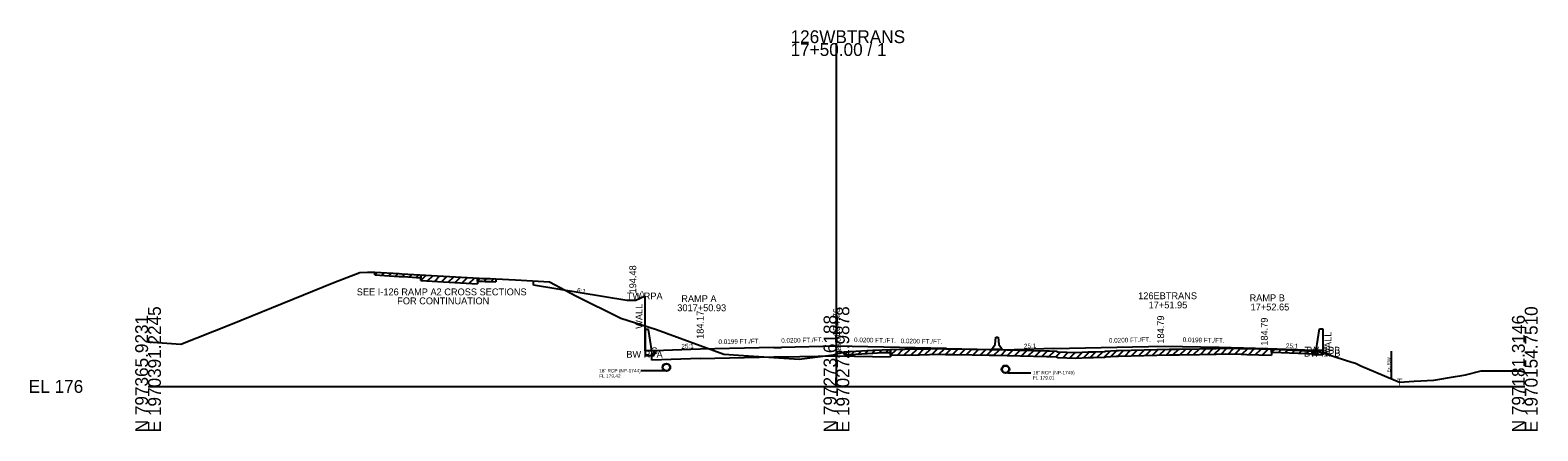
# Model space of a CAD drawing. Extents: x -6494 to 1970605, y -10 to 798140.
# Drawn here: x 974.3 to 1302.8, y -9.7 to 77.8 of the extents above; entities that cross this region are included whole.
import ezdxf

# ---------------------------------------------------------------- set-up
doc = ezdxf.new("R2010")
doc.units = 0
for name, color, linetype in [('Default', 7, 'Continuous'), ('RD_EX_SU_Misc_TxCode', 7, 'Continuous'), ('RD_GPK_XS_Cell', 7, 'Continuous'), ('RD_Sketch1', 7, 'Continuous'), ('RD_XS_Base', 7, 'Continuous'), ('RD_XS_Box', 7, 'Continuous'), ('RD_XS_EwShp', 7, 'Continuous'), ('RD_XS_ExGround', 7, 'Continuous'), ('RD_XS_ExPaveRet', 7, 'Continuous'), ('RD_XS_ExRW', 7, 'Continuous'), ('RD_XS_MedBWall', 7, 'Continuous'), ('RD_XS_Misc_Line', 7, 'Continuous'), ('RD_XS_Pave', 7, 'Continuous'), ('RD_XS_PaveOvlay', 7, 'Continuous'), ('RD_XS_PaveShd', 7, 'Continuous'), ('RD_XS_Pipe', 7, 'Continuous'), ('RD_XS_TieSlope', 7, 'Continuous'), ('RD_XS_TX_Elev_EX', 7, 'Continuous'), ('RD_XS_TX_Elev_PR', 7, 'Continuous'), ('RD_XS_TX_Misc', 7, 'Continuous'), ('RD_XS_TX_Notes', 7, 'Continuous'), ('RD_XS_TX_Profile', 7, 'Continuous'), ('RD_XS_TX_Slope', 7, 'Continuous'), ('RD_XS_TX_Station', 7, 'Continuous')]:
    doc.layers.add(name, color=color, linetype=linetype)

msp = doc.modelspace()

# ---------------------------------------------------------------- linework, layer by layer
at = {"layer": 'Default'}
for p, q in [((1184.58, 9.18), (1184.75, 10.77)), ((1184.75, 10.77), (1185.25, 10.77)), ((1185.25, 10.77), (1185.42, 9.18)), ((1184, 8.35), (1184.58, 9.18)), ((1184, 8.1), (1184, 8.35)), ((1186, 8.1), (1184, 8.1)), ((1185.42, 9.18), (1186, 8.35)), ((1186, 8.35), (1186, 8.1))]:
    msp.add_line(p, q, dxfattribs=at)
at = {"layer": 'RD_GPK_XS_Cell'}
for p, q in [((1150, 0), (1150, 74.92)), ((1000, 0), (1150, 0)), ((1150, 0), (1300, 0))]:
    msp.add_line(p, q, dxfattribs=at)
at = {"layer": 'RD_XS_Base'}
for p, q in [((1109.79, 7.19), (1110.29, 7.21)), ((1109.79, 5.71), (1109.79, 7.19)), ((1110.29, 7.21), (1110.29, 7.77)), ((1138, 6.48), (1150, 6.72)), ((1150, 6.72), (1161.78, 6.49)), ((1254.02, 7.72), (1254.02, 7.94)), ((1254.02, 7.38), (1254.02, 7.94)), ((1120.31, 6.13), (1109.79, 5.71)), ((1120.31, 6.13), (1136.33, 6.45)), ((1136.33, 6.45), (1138, 6.48))]:
    msp.add_line(p, q, dxfattribs=at)
at = {"layer": 'RD_XS_Box'}
for p, q in [((1108.29, 7.77), (1108.29, 19.73)), ((1110.29, 7.77), (1108.29, 7.77)), ((1254.02, 7.94), (1256.03, 7.94)), ((1256.03, 7.94), (1256.03, 7.3))]:
    msp.add_line(p, q, dxfattribs=at)
at = {"layer": 'RD_XS_ExGround'}
msp.add_lwpolyline([(1000, 9.72), (1007.13, 9.22), (1017.96, 13.51), (1040.47, 22.69), (1046.17, 24.84), (1047.78, 24.92), (1049.42, 24.97), (1054.7, 24.64), (1055.28, 24.61), (1056.64, 24.53), (1072.16, 23.61), (1072.89, 23.59), (1073.44, 23.57), (1074.56, 23.53), (1075.75, 23.49), (1080.09, 23.24), (1087.46, 22.8), (1093.19, 19.76), (1103.04, 14.89), (1110.8, 12.4), (1125.45, 7.04), (1129.74, 6.74), (1141.91, 5.94), (1148.78, 6.85), (1149.35, 6.93), (1150, 7.09), (1150.71, 7.27), (1151.78, 7.53), (1157.93, 7.91), (1159.93, 8.03), (1161.74, 8.07), (1168.1, 8.18), (1170.27, 8.23), (1172, 8.27), (1173.79, 8.24), (1175.78, 8.2), (1183.25, 8.08), (1183.66, 8.07), (1184.33, 8.06), (1195.8, 7.81), (1196.44, 7.78), (1197.98, 7.7), (1198.26, 7.58), (1202.17, 7.4), (1204.84, 7.54), (1206.03, 7.59), (1208.43, 7.66), (1208.65, 7.74), (1210.98, 7.85), (1211.46, 7.86), (1222.55, 8.12), (1224.74, 8.15), (1229.1, 8.24), (1232.76, 8.29), (1234.77, 8.34), (1238.21, 8.27), (1239.43, 8.25), (1242.05, 8.18), (1246.88, 8.05), (1252.46, 7.8), (1254.81, 7.69), (1260.71, 5.82), (1262.32, 5.31), (1263.07, 5.08), (1264.29, 4.52), (1272.67, 0.96), (1275.87, 1.15), (1280.16, 1.41), (1284.88, 2.16), (1286.27, 2.37), (1287.09, 2.57), (1290.51, 3.41), (1296.88, 3.41), (1299.09, 3.41), (1300, 3.1)], dxfattribs=at)
at = {"layer": 'RD_XS_ExPaveRet'}
for p, q in [((1049.42, 24.35), (1049.42, 24.97)), ((1049.42, 24.35), (1054.7, 24.02)), ((1054.7, 24.02), (1055.28, 23.98)), ((1055.28, 23.98), (1056.64, 23.9)), ((1056.64, 23.9), (1059.42, 23.74)), ((1059.42, 23.11), (1059.42, 24.36)), ((1059.42, 24.36), (1059.42, 23.74)), ((1059.42, 23.11), (1071.75, 22.39)), ((1071.75, 23.64), (1071.75, 22.39)), ((1071.75, 23.01), (1071.75, 23.64)), ((1071.75, 23.01), (1072.16, 22.99)), ((1075.75, 23.49), (1075.75, 22.86)), ((1072.16, 22.99), (1072.89, 22.96)), ((1072.89, 22.96), (1073.44, 22.94)), ((1073.44, 22.94), (1074.56, 22.9)), ((1074.56, 22.9), (1075.75, 22.86)), ((1151.78, 6.91), (1151.78, 7.53)), ((1151.78, 6.91), (1157.93, 7.29)), ((1157.93, 7.29), (1159.93, 7.41)), ((1159.93, 7.41), (1161.74, 7.44)), ((1161.74, 7.44), (1161.78, 7.45)), ((1161.78, 6.82), (1161.78, 8.07)), ((1161.78, 8.07), (1161.78, 7.45)), ((1161.78, 6.82), (1168.1, 6.93)), ((1168.1, 6.93), (1170.27, 6.98)), ((1170.27, 6.98), (1172, 7.02)), ((1172, 7.02), (1173.79, 6.99)), ((1173.79, 6.99), (1175.78, 6.95)), ((1175.78, 6.95), (1183.25, 6.83)), ((1183.25, 6.83), (1183.66, 6.82)), ((1183.66, 6.82), (1184.33, 6.81)), ((1184.33, 6.81), (1195.8, 6.56)), ((1208.65, 6.49), (1210.98, 6.6)), ((1210.98, 6.6), (1211.46, 6.61)), ((1211.46, 6.61), (1222.55, 6.87)), ((1222.55, 6.87), (1224.74, 6.9)), ((1224.74, 6.9), (1229.1, 6.99)), ((1229.1, 6.99), (1232.76, 7.04)), ((1232.76, 7.04), (1234.77, 7.09)), ((1234.77, 7.09), (1238.21, 7.02)), ((1238.21, 7.02), (1239.43, 7)), ((1239.43, 7), (1242.05, 6.93)), ((1242.05, 6.93), (1244.81, 6.86)), ((1244.81, 8.11), (1244.81, 6.86)), ((1244.81, 7.48), (1244.81, 8.11)), ((1244.81, 7.48), (1246.88, 7.43)), ((1246.88, 7.43), (1252.46, 7.18)), ((1252.46, 7.18), (1254.81, 7.06)), ((1254.81, 7.69), (1254.81, 7.06)), ((1195.8, 6.56), (1196.44, 6.53)), ((1196.44, 6.53), (1197.98, 6.45)), ((1197.98, 6.45), (1198.26, 6.33)), ((1198.26, 6.33), (1202.17, 6.15)), ((1202.17, 6.15), (1204.84, 6.29)), ((1204.84, 6.29), (1206.03, 6.34)), ((1206.03, 6.34), (1208.43, 6.41)), ((1208.43, 6.41), (1208.65, 6.49))]:
    msp.add_line(p, q, dxfattribs=at)
at = {"layer": 'RD_XS_ExRW'}
msp.add_line((1270.91, 7.7), (1270.91, 1.7), dxfattribs=at)
at = {"layer": 'RD_XS_MedBWall'}
for p, q in [((1109.04, 12.44), (1108.29, 12.44)), ((1108.29, 12.44), (1108.29, 6.77)), ((1109.79, 7.77), (1109.04, 12.44)), ((1254.52, 7.94), (1255.27, 12.6)), ((1255.27, 12.6), (1256.02, 12.6)), ((1256.02, 12.6), (1256.02, 6.94)), ((1108.29, 6.77), (1110.29, 6.77)), ((1110.29, 7.77), (1109.79, 7.77)), ((1110.29, 6.77), (1110.29, 7.77)), ((1254.02, 6.94), (1254.02, 7.94)), ((1254.02, 7.94), (1254.52, 7.94)), ((1256.02, 6.94), (1254.02, 6.94))]:
    msp.add_line(p, q, dxfattribs=at)
at = {"layer": 'RD_XS_Misc_Line'}
for p, q in [((1049.42, 24.35), (1050, 24.94)), ((1050.92, 24.26), (1051.51, 24.84)), ((1052.42, 24.16), (1053.01, 24.75)), ((1053.92, 24.07), (1054.51, 24.66)), ((1055.42, 23.98), (1056.01, 24.56)), ((1056.92, 23.88), (1057.51, 24.47)), ((1058.42, 23.8), (1059.01, 24.39)), ((1059.42, 23.11), (1060.6, 24.29)), ((1060.92, 23.02), (1062.1, 24.2)), ((1062.42, 22.94), (1063.6, 24.12)), ((1063.92, 22.85), (1065.11, 24.03)), ((1065.43, 22.76), (1066.61, 23.94)), ((1066.93, 22.67), (1068.11, 23.85)), ((1068.43, 22.58), (1069.61, 23.76)), ((1069.93, 22.49), (1071.11, 23.67)), ((1071.75, 23.01), (1072.34, 23.61)), ((1073.25, 22.95), (1073.85, 23.55)), ((1074.75, 22.9), (1075.35, 23.5)), ((1151.78, 6.91), (1152.45, 7.58)), ((1153.29, 7), (1153.95, 7.67)), ((1154.79, 7.1), (1155.45, 7.76)), ((1156.29, 7.19), (1156.95, 7.85)), ((1157.79, 7.28), (1158.45, 7.95)), ((1159.29, 7.37), (1159.95, 8.03)), ((1160.79, 7.43), (1161.43, 8.06)), ((1161.78, 6.82), (1163.06, 8.09)), ((1163.29, 6.85), (1164.56, 8.12)), ((1164.79, 6.87), (1166.06, 8.14)), ((1166.29, 6.9), (1167.56, 8.17)), ((1167.79, 6.92), (1169.07, 8.2)), ((1169.29, 6.96), (1170.57, 8.24)), ((1170.79, 6.99), (1172.07, 8.27)), ((1172.29, 7.02), (1173.52, 8.24)), ((1173.79, 6.99), (1175.02, 8.22)), ((1175.29, 6.96), (1176.52, 8.19)), ((1176.79, 6.94), (1178.02, 8.17)), ((1178.29, 6.91), (1179.52, 8.14)), ((1179.8, 6.89), (1181.02, 8.11)), ((1181.3, 6.86), (1182.53, 8.09)), ((1182.8, 6.83), (1184.03, 8.06)), ((1184.3, 6.81), (1185.52, 8.03)), ((1185.8, 6.77), (1187.02, 8)), ((1187.3, 6.74), (1188.52, 7.97)), ((1188.8, 6.71), (1190.03, 7.93)), ((1190.3, 6.68), (1191.53, 7.9)), ((1191.8, 6.65), (1193.03, 7.87)), ((1193.3, 6.62), (1194.53, 7.84)), ((1194.8, 6.58), (1196.02, 7.8)), ((1196.3, 6.54), (1197.49, 7.73)), ((1197.81, 6.46), (1198.9, 7.55)), ((1199.31, 6.28), (1200.5, 7.48)), ((1200.81, 6.21), (1202, 7.41)), ((1202.31, 6.16), (1203.63, 7.47)), ((1203.81, 6.23), (1205.12, 7.55)), ((1205.31, 6.31), (1206.61, 7.6)), ((1206.81, 6.36), (1208.1, 7.65)), ((1208.31, 6.41), (1209.7, 7.79)), ((1209.81, 6.55), (1211.12, 7.85)), ((1211.31, 6.61), (1212.59, 7.89)), ((1212.81, 6.64), (1214.09, 7.92)), ((1214.31, 6.68), (1215.6, 7.96)), ((1215.82, 6.71), (1217.1, 7.99)), ((1217.32, 6.75), (1218.6, 8.03)), ((1218.82, 6.78), (1220.1, 8.06)), ((1220.32, 6.82), (1221.6, 8.1)), ((1221.82, 6.85), (1223.09, 8.12)), ((1223.32, 6.88), (1224.59, 8.14)), ((1224.82, 6.9), (1226.1, 8.17)), ((1226.32, 6.93), (1227.6, 8.21)), ((1227.82, 6.96), (1229.1, 8.24)), ((1229.32, 6.99), (1230.59, 8.26)), ((1230.82, 7.01), (1232.09, 8.28)), ((1232.33, 7.03), (1233.6, 8.31)), ((1233.83, 7.06), (1235.09, 8.33)), ((1235.33, 7.07), (1236.55, 8.3)), ((1236.83, 7.05), (1238.05, 8.27)), ((1238.33, 7.02), (1239.55, 8.24)), ((1239.83, 6.99), (1241.05, 8.2)), ((1241.33, 6.95), (1242.55, 8.16)), ((1242.83, 6.91), (1244.05, 8.13)), ((1244.81, 7.48), (1245.42, 8.09)), ((1246.31, 7.44), (1246.92, 8.05)), ((1247.81, 7.39), (1248.41, 7.98)), ((1249.32, 7.32), (1249.91, 7.92)), ((1250.82, 7.25), (1251.41, 7.85)), ((1252.32, 7.18), (1252.91, 7.78)), ((1253.82, 7.11), (1254.41, 7.71))]:
    msp.add_line(p, q, dxfattribs=at)
at = {"layer": 'RD_XS_Pave'}
for p, q in [((1136.33, 8.49), (1120.31, 8.17)), ((1150, 8.76), (1138, 8.52)), ((1174, 8.28), (1150, 8.76)), ((1197.4, 8.31), (1221.4, 8.79)), ((1221.4, 8.79), (1233.4, 8.55)), ((1233.4, 8.55), (1243.99, 8.31))]:
    msp.add_line(p, q, dxfattribs=at)
at = {"layer": 'RD_XS_PaveOvlay'}
for p, q in [((1161.78, 8.07), (1168.1, 8.18)), ((1161.78, 8.07), (1161.78, 6.49)), ((1168.1, 8.18), (1170.27, 8.23)), ((1170.27, 8.23), (1172, 8.27)), ((1172, 8.27), (1173.79, 8.24)), ((1173.79, 8.24), (1175.78, 8.2)), ((1175.78, 8.2), (1183.25, 8.08)), ((1183.25, 8.08), (1183.66, 8.07)), ((1183.66, 8.07), (1184.33, 8.06)), ((1184.33, 8.06), (1195.8, 7.81)), ((1195.8, 7.81), (1196.44, 7.78)), ((1196.44, 7.78), (1197.98, 7.7)), ((1197.98, 7.7), (1198.26, 7.58)), ((1198.26, 7.58), (1202.17, 7.4)), ((1202.17, 7.4), (1204.84, 7.54)), ((1204.84, 7.54), (1206.03, 7.59)), ((1206.03, 7.59), (1208.43, 7.66)), ((1208.43, 7.66), (1208.65, 7.74)), ((1208.65, 7.74), (1210.98, 7.85)), ((1210.98, 7.85), (1211.46, 7.86)), ((1211.46, 7.86), (1222.55, 8.12)), ((1222.55, 8.12), (1224.74, 8.15)), ((1224.74, 8.15), (1229.1, 8.24)), ((1229.1, 8.24), (1232.76, 8.29)), ((1232.76, 8.29), (1234.77, 8.34)), ((1234.77, 8.34), (1238.21, 8.27)), ((1238.21, 8.27), (1239.43, 8.25)), ((1239.43, 8.25), (1242.05, 8.18)), ((1242.05, 8.18), (1244.81, 8.11)), ((1244.81, 8.11), (1246.88, 8.05)), ((1246.88, 8.05), (1249.67, 7.93)), ((1249.67, 7.93), (1252.46, 7.8)), ((1252.46, 7.8), (1253.64, 7.74)), ((1253.64, 7.74), (1254.02, 7.72))]:
    msp.add_line(p, q, dxfattribs=at)
at = {"layer": 'RD_XS_PaveShd'}
for p, q in [((1120.31, 8.17), (1110.29, 7.77)), ((1136.33, 8.49), (1138, 8.52)), ((1174, 8.28), (1184, 8.06)), ((1184, 8.06), (1188.75, 7.96)), ((1197.4, 8.31), (1188.75, 7.96)), ((1243.99, 8.31), (1254.02, 7.91))]:
    msp.add_line(p, q, dxfattribs=at)
at = {"layer": 'RD_XS_Pipe'}
for p, q in [((1112.45, 3.42), (1107.45, 3.42)), ((1187.35, 3.01), (1192.35, 3.01))]:
    msp.add_line(p, q, dxfattribs=at)
for centre, radius in [((1112.95, 4.17), 0.85), ((1112.95, 4.17), 0.75), ((1186.85, 3.76), 0.85), ((1186.85, 3.76), 0.75)]:
    msp.add_circle(centre, radius, dxfattribs=at)
at = {"layer": 'RD_XS_TieSlope'}
for p, q in [((1083.97, 22.12), (1083.97, 23.01)), ((1104.29, 18.73), (1083.97, 22.12)), ((1108.29, 19.73), (1106.29, 18.73)), ((1106.29, 18.73), (1104.29, 18.73))]:
    msp.add_line(p, q, dxfattribs=at)

# ---------------------------------------------------------------- texts
at = {"layer": 'RD_EX_SU_Misc_TxCode'}
msp.add_text('G', height=1.5, dxfattribs=at).set_placement((1109.54, 7.02))
at = {"layer": 'RD_GPK_XS_Cell'}
for s, p in [('126WBTRANS', (1140, 74.92)), ('17+50.00 / 1', (1140, 72.12)), ('EL 176', (974, -1.4))]:
    msp.add_text(s, height=2.8, dxfattribs=at).set_placement(p)
for s, p in [('E 1970391.2245', (1002.8, -10)), ('E 1970272.9878', (1152.8, -10)), ('E 1970154.7510', (1302.8, -10)), ('N 797365.9231', (1000, -10)), ('N 797273.6188', (1150, -10)), ('N 797181.3146', (1300, -10))]:
    msp.add_text(s, height=2.8, rotation=90, dxfattribs=at).set_placement(p)
at = {"layer": 'RD_Sketch1'}
msp.add_text('T', height=1.5, dxfattribs=at).set_placement((1272.12, 0.21))
at = {"layer": 'RD_XS_EwShp'}
for s, p in [('TW RPA', (1104.33, 18.98)), ('BW RPA', (1104.22, 6.27)), ('TW RPB', (1252, 7.16)), ('BW RPB', (1251.9, 6.52))]:
    msp.add_text(s, height=1.5, dxfattribs=at).set_placement(p)
at = {"layer": 'RD_XS_ExRW'}
msp.add_text('Ex. R/W ', height=0.65, rotation=90, dxfattribs=at).set_placement((1270.66, 3.09))
at = {"layer": 'RD_XS_Pipe'}
for s, p in [('18" RCP (NP-1744)', (1098.3, 3.05)), ('18" RCP (NP-1749)', (1192.85, 2.64)), ('FL 179.42', (1098.3, 1.92)), ('FL 179.01', (1192.85, 1.51))]:
    msp.add_text(s, height=0.75, dxfattribs=at).set_placement(p)
at = {"layer": 'RD_XS_TX_Elev_EX'}
msp.add_text('183.09', height=1, rotation=90, dxfattribs=at).set_placement((1151, 7.09))
at = {"layer": 'RD_XS_TX_Elev_PR'}
for s, p in [('184.76', (1150.75, 10.98)), ('184.17', (1121.06, 10.38)), (' 184.79', (1221.4, 8.79)), (' 184.79', (1243.99, 8.34))]:
    msp.add_text(s, height=1.5, rotation=90, dxfattribs=at).set_placement(p)
at = {"layer": 'RD_XS_TX_Misc'}
msp.add_text('194.48', height=1.5, rotation=90, dxfattribs=at).set_placement((1106.37, 20.31))
at = {"layer": 'RD_XS_TX_Notes'}
for s, p in [('SEE I-126 RAMP A2 CROSS SECTIONS', (1045.48, 19.89)), ('FOR CONTINUATION', (1054.29, 17.93))]:
    msp.add_text(s, height=1.5, dxfattribs=at).set_placement(p)
for p in [(1107.72, 12.58), (1257.84, 6.5)]:
    msp.add_text('WALL', height=1.5, rotation=90, dxfattribs=at).set_placement(p)
at = {"layer": 'RD_XS_TX_Profile'}
for rotation, p in [(2.2905, (1190.88, 8.3)), (357.7094, (1247.93, 8.4))]:
    msp.add_text('25:1', height=1, rotation=rotation, dxfattribs=at).set_placement(p)
at = {"layer": 'RD_XS_TX_Slope'}
for s, rotation, p in [('6:1', 350.5377, (1093.41, 20.54)), ('2:1', 26.5651, (1106.69, 19.24)), ('0.0199 FT./FT.', 1.1389, (1124.3, 9.25)), ('0.0200 FT./FT.', 1.1458, (1137.98, 9.52)), ('0.0200 FT./FT.', 358.8542, (1153.83, 9.69)), ('0.0200 FT./FT.', 358.8542, (1163.98, 9.46)), ('0.0200 FT./FT.', 1.146, (1209.38, 9.55)), ('0.0199 FT./FT.', 358.8577, (1225.45, 9.71)), ('25:1', 2.287, (1116.24, 8.26))]:
    msp.add_text(s, height=1, rotation=rotation, dxfattribs=at).set_placement(p)
at = {"layer": 'RD_XS_TX_Station'}
for s, p in [('RAMP A', (1116.19, 18.42)), ('126EBTRANS', (1215.75, 19.04)), ('RAMP B', (1240.03, 18.59)), ('3017+50.93', (1115.32, 16.42)), ('17+51.95', (1218.03, 17.04)), ('17+52.65', (1240.25, 16.59))]:
    msp.add_text(s, height=1.5, dxfattribs=at).set_placement(p)

doc.saveas('drawing.dxf')
